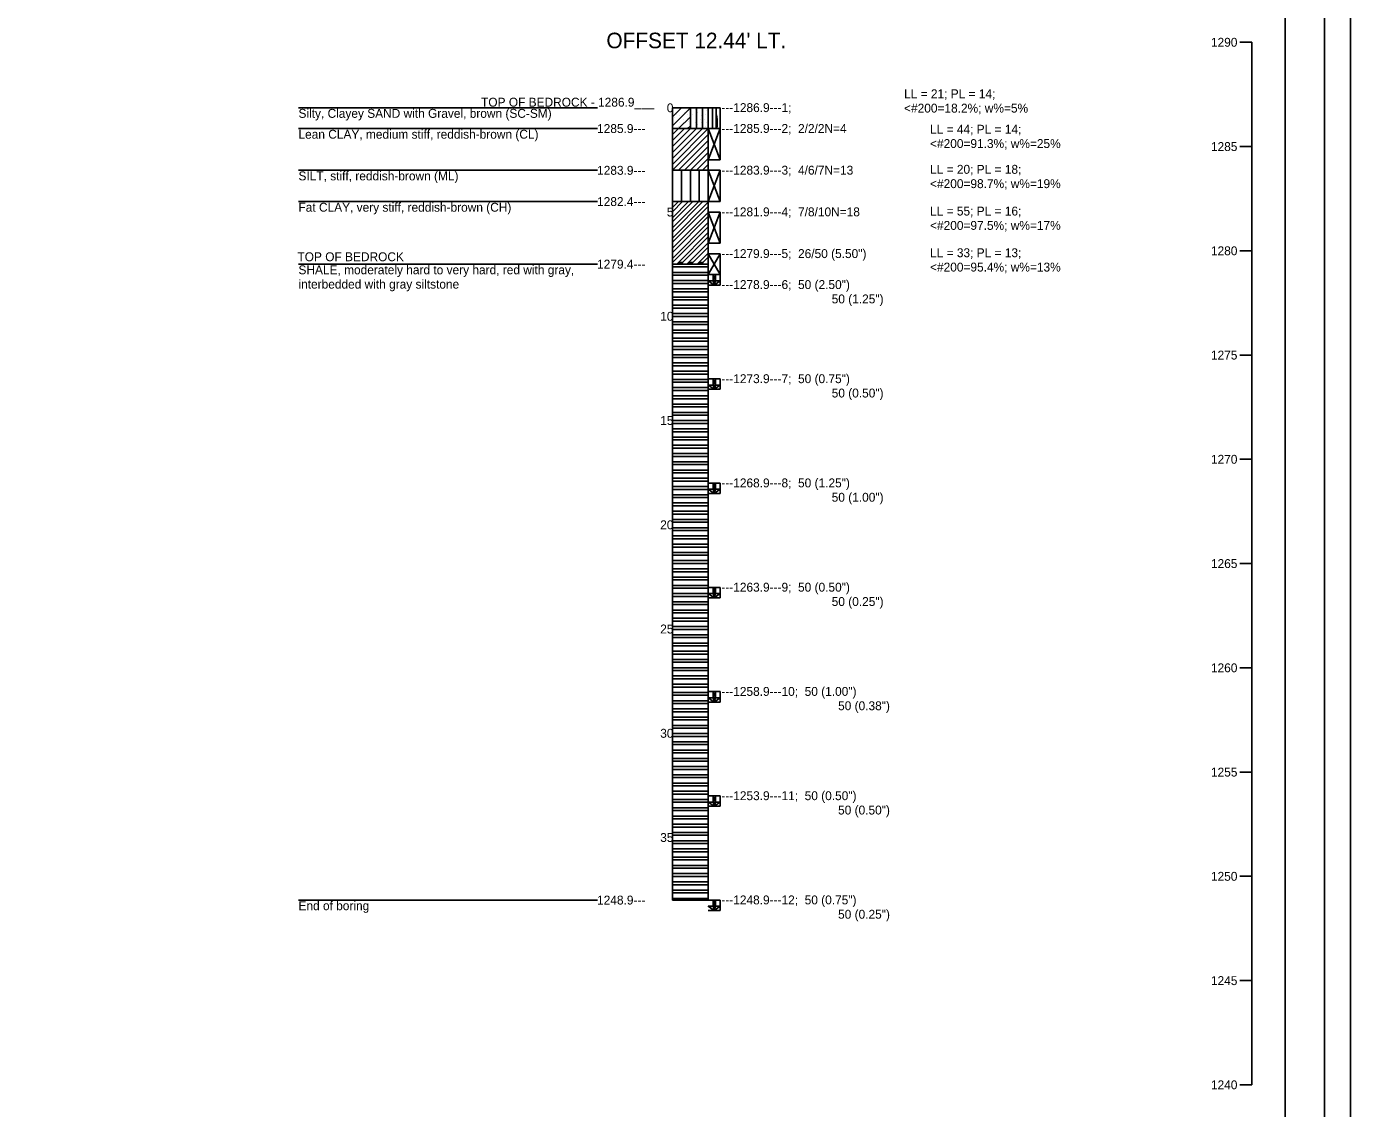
# Model space of a CAD drawing. Extents: x -6 to 173, y 24 to 64.
# Drawn here: x 24.17 to 42.62, y 35.63 to 50.71 of the extents above; entities that cross this region are included whole.
import ezdxf

# ---------------------------------------------------------------- set-up
doc = ezdxf.new("R2010")
doc.units = 0
for name, color, linetype in [('SHT_Plot_Shape_Full', 7, 'Continuous'), ('SHT_Plot_Shape_Half', 7, 'Continuous'), ('SHT_Sheet_Border', 7, 'Continuous')]:
    doc.layers.add(name, color=color, linetype=linetype)

# ---------------------------------------------------------------- blocks, each defined once
blk = doc.blocks.new('POINT_DISPLAY')
blk.add_line((0, 0), (0, 0))

msp = doc.modelspace()

# ---------------------------------------------------------------- linework, layer by layer
msp.add_line((41.25, 35.958), (41.25, 50.493))
for points in [[(41.25, 50.493), (41.083, 50.493)], [(27.961, 49.58), (32.127, 49.58)], [(33.173, 49.455), (33.298, 49.58)], [(33.173, 49.33), (33.423, 49.58)], [(33.173, 49.58), (33.173, 38.534)], [(33.173, 49.58), (33.673, 49.58)], [(33.423, 49.29), (33.423, 49.58)], [(33.507, 49.29), (33.507, 49.58)], [(33.59, 49.29), (33.59, 49.58)], [(33.673, 49.58), (33.84, 49.58)], [(33.673, 49.58), (33.673, 38.534)], [(33.84, 49.29), (33.84, 49.58)], [(27.961, 49.29), (32.127, 49.29)], [(33.173, 49.29), (33.673, 49.29)], [(33.173, 49.206), (33.257, 49.29)], [(33.173, 49.123), (33.34, 49.29)], [(33.173, 49.04), (33.423, 49.29)], [(33.173, 48.956), (33.507, 49.29)], [(33.173, 48.873), (33.59, 49.29)], [(33.173, 48.79), (33.673, 49.29)], [(33.257, 49.29), (33.423, 49.455)], [(33.382, 49.29), (33.423, 49.33)], [(33.673, 49.29), (33.84, 49.29)], [(33.673, 49.29), (33.84, 48.854)], [(33.673, 48.854), (33.84, 49.29)], [(33.673, 49.29), (33.84, 49.29)], [(33.84, 48.854), (33.84, 49.29)], [(33.175, 48.708), (33.673, 49.206)], [(33.258, 48.708), (33.673, 49.123)], [(33.342, 48.708), (33.673, 49.04)], [(33.425, 48.708), (33.673, 48.956)], [(41.25, 49.039), (41.083, 49.039)], [(33.508, 48.708), (33.673, 48.873)], [(33.592, 48.708), (33.673, 48.79)], [(33.673, 48.854), (33.84, 48.854)], [(27.961, 48.708), (32.127, 48.708)], [(33.173, 48.708), (33.673, 48.708)], [(33.298, 48.272), (33.298, 48.708)], [(33.423, 48.272), (33.423, 48.708)], [(33.548, 48.272), (33.548, 48.708)], [(33.673, 48.708), (33.84, 48.272)], [(33.673, 48.272), (33.84, 48.708)], [(33.673, 48.708), (33.84, 48.708)], [(33.84, 48.272), (33.84, 48.708)], [(27.961, 48.272), (32.127, 48.272)], [(33.173, 48.272), (33.673, 48.272)], [(33.673, 48.272), (33.84, 48.272)], [(33.673, 48.127), (33.84, 47.691)], [(33.673, 47.691), (33.84, 48.127)], [(33.673, 48.127), (33.84, 48.127)], [(33.84, 47.691), (33.84, 48.127)], [(33.673, 47.691), (33.84, 47.691)], [(33.673, 47.545), (33.84, 47.255)], [(33.673, 47.255), (33.84, 47.545)], [(33.673, 47.545), (33.84, 47.545)], [(33.84, 47.255), (33.84, 47.545)], [(41.25, 47.586), (41.083, 47.586)], [(27.961, 47.4), (32.127, 47.4)], [(33.173, 47.4), (33.673, 47.4)], [(33.173, 47.4), (33.673, 47.4)], [(33.173, 47.361), (33.673, 47.361)], [(33.173, 47.285), (33.673, 47.285)], [(33.173, 47.246), (33.673, 47.246)], [(33.673, 47.255), (33.84, 47.255)], [(33.673, 47.255), (33.84, 47.255)], [(33.84, 47.109), (33.84, 47.255)], [(33.173, 47.17), (33.673, 47.17)], [(33.173, 47.131), (33.673, 47.131)], [(33.673, 47.109), (33.84, 47.109)], [(33.173, 47.056), (33.673, 47.056)], [(33.173, 47.016), (33.673, 47.016)], [(33.173, 46.941), (33.673, 46.941)], [(33.173, 46.901), (33.673, 46.901)], [(33.173, 46.826), (33.673, 46.826)], [(33.173, 46.787), (33.673, 46.787)], [(33.173, 46.711), (33.673, 46.711)], [(33.173, 46.672), (33.673, 46.672)], [(33.173, 46.596), (33.673, 46.596)], [(33.173, 46.557), (33.673, 46.557)], [(33.173, 46.481), (33.673, 46.481)], [(33.173, 46.442), (33.673, 46.442)], [(33.173, 46.367), (33.673, 46.367)], [(33.173, 46.327), (33.673, 46.327)], [(33.173, 46.252), (33.673, 46.252)], [(33.173, 46.212), (33.673, 46.212)], [(33.173, 46.137), (33.673, 46.137)], [(33.173, 46.098), (33.673, 46.098)], [(33.173, 46.022), (33.673, 46.022)], [(33.173, 45.983), (33.673, 45.983)], [(41.25, 46.132), (41.083, 46.132)], [(33.173, 45.907), (33.673, 45.907)], [(33.173, 45.868), (33.673, 45.868)], [(33.173, 45.792), (33.673, 45.792)], [(33.673, 45.801), (33.84, 45.801)], [(33.84, 45.656), (33.84, 45.801)], [(33.173, 45.753), (33.673, 45.753)], [(33.173, 45.678), (33.673, 45.678)], [(33.173, 45.638), (33.673, 45.638)], [(33.673, 45.656), (33.84, 45.656)], [(33.173, 45.563), (33.673, 45.563)], [(33.173, 45.523), (33.673, 45.523)], [(33.173, 45.448), (33.673, 45.448)], [(33.173, 45.409), (33.673, 45.409)], [(33.173, 45.333), (33.673, 45.333)], [(33.173, 45.294), (33.673, 45.294)], [(33.173, 45.218), (33.673, 45.218)], [(33.173, 45.179), (33.673, 45.179)], [(33.173, 45.103), (33.673, 45.103)], [(33.173, 45.064), (33.673, 45.064)], [(33.173, 44.989), (33.673, 44.989)], [(33.173, 44.949), (33.673, 44.949)], [(33.173, 44.874), (33.673, 44.874)], [(33.173, 44.834), (33.673, 44.834)], [(33.173, 44.759), (33.673, 44.759)], [(33.173, 44.72), (33.673, 44.72)], [(41.25, 44.679), (41.083, 44.679)], [(33.173, 44.644), (33.673, 44.644)], [(33.173, 44.605), (33.673, 44.605)], [(33.173, 44.529), (33.673, 44.529)], [(33.173, 44.49), (33.673, 44.49)], [(33.173, 44.414), (33.673, 44.414)], [(33.173, 44.375), (33.673, 44.375)], [(33.173, 44.3), (33.673, 44.3)], [(33.673, 44.348), (33.84, 44.348)], [(33.84, 44.202), (33.84, 44.348)], [(33.173, 44.26), (33.673, 44.26)], [(33.173, 44.185), (33.673, 44.185)], [(33.173, 44.145), (33.673, 44.145)], [(33.673, 44.202), (33.84, 44.202)], [(33.173, 44.07), (33.673, 44.07)], [(33.173, 44.031), (33.673, 44.031)], [(33.173, 43.955), (33.673, 43.955)], [(33.173, 43.916), (33.673, 43.916)], [(33.173, 43.84), (33.673, 43.84)], [(33.173, 43.801), (33.673, 43.801)], [(33.173, 43.726), (33.673, 43.726)], [(33.173, 43.686), (33.673, 43.686)], [(33.173, 43.611), (33.673, 43.611)], [(33.173, 43.571), (33.673, 43.571)], [(33.173, 43.496), (33.673, 43.496)], [(33.173, 43.456), (33.673, 43.456)], [(33.173, 43.381), (33.673, 43.381)], [(33.173, 43.342), (33.673, 43.342)], [(33.173, 43.266), (33.673, 43.266)], [(33.173, 43.227), (33.673, 43.227)], [(41.25, 43.225), (41.083, 43.225)], [(33.173, 43.151), (33.673, 43.151)], [(33.173, 43.112), (33.673, 43.112)], [(33.173, 43.037), (33.673, 43.037)], [(33.173, 42.997), (33.673, 42.997)], [(33.173, 42.922), (33.673, 42.922)], [(33.173, 42.882), (33.673, 42.882)], [(33.673, 42.894), (33.84, 42.894)], [(33.84, 42.749), (33.84, 42.894)], [(33.173, 42.807), (33.673, 42.807)], [(33.173, 42.768), (33.673, 42.768)], [(33.173, 42.692), (33.673, 42.692)], [(33.173, 42.653), (33.673, 42.653)], [(33.673, 42.749), (33.84, 42.749)], [(33.173, 42.577), (33.673, 42.577)], [(33.173, 42.538), (33.673, 42.538)], [(33.173, 42.462), (33.673, 42.462)], [(33.173, 42.423), (33.673, 42.423)], [(33.173, 42.348), (33.673, 42.348)], [(33.173, 42.308), (33.673, 42.308)], [(33.173, 42.233), (33.673, 42.233)], [(33.173, 42.193), (33.673, 42.193)], [(33.173, 42.118), (33.673, 42.118)], [(33.173, 42.079), (33.673, 42.079)], [(33.173, 42.003), (33.673, 42.003)], [(33.173, 41.964), (33.673, 41.964)], [(33.173, 41.888), (33.673, 41.888)], [(33.173, 41.849), (33.673, 41.849)], [(33.173, 41.773), (33.673, 41.773)], [(33.173, 41.734), (33.673, 41.734)], [(41.25, 41.772), (41.083, 41.772)], [(33.173, 41.659), (33.673, 41.659)], [(33.173, 41.619), (33.673, 41.619)], [(33.173, 41.544), (33.673, 41.544)], [(33.173, 41.504), (33.673, 41.504)], [(33.173, 41.429), (33.673, 41.429)], [(33.173, 41.39), (33.673, 41.39)], [(33.673, 41.441), (33.84, 41.441)], [(33.84, 41.295), (33.84, 41.441)], [(33.173, 41.314), (33.673, 41.314)], [(33.173, 41.275), (33.673, 41.275)], [(33.173, 41.199), (33.673, 41.199)], [(33.173, 41.16), (33.673, 41.16)], [(33.673, 41.295), (33.84, 41.295)], [(33.173, 41.084), (33.673, 41.084)], [(33.173, 41.045), (33.673, 41.045)], [(33.173, 40.97), (33.673, 40.97)], [(33.173, 40.93), (33.673, 40.93)], [(33.173, 40.855), (33.673, 40.855)], [(33.173, 40.815), (33.673, 40.815)], [(33.173, 40.74), (33.673, 40.74)], [(33.173, 40.701), (33.673, 40.701)], [(33.173, 40.625), (33.673, 40.625)], [(33.173, 40.586), (33.673, 40.586)], [(33.173, 40.51), (33.673, 40.51)], [(33.173, 40.471), (33.673, 40.471)], [(33.173, 40.395), (33.673, 40.395)], [(33.173, 40.356), (33.673, 40.356)], [(33.173, 40.281), (33.673, 40.281)], [(33.173, 40.241), (33.673, 40.241)], [(41.25, 40.318), (41.083, 40.318)], [(33.173, 40.166), (33.673, 40.166)], [(33.173, 40.126), (33.673, 40.126)], [(33.173, 40.051), (33.673, 40.051)], [(33.173, 40.012), (33.673, 40.012)], [(33.173, 39.936), (33.673, 39.936)], [(33.173, 39.897), (33.673, 39.897)], [(33.673, 39.987), (33.84, 39.987)], [(33.84, 39.842), (33.84, 39.987)], [(33.173, 39.821), (33.673, 39.821)], [(33.173, 39.782), (33.673, 39.782)], [(33.173, 39.706), (33.673, 39.706)], [(33.673, 39.842), (33.84, 39.842)], [(33.173, 39.667), (33.673, 39.667)], [(33.173, 39.592), (33.673, 39.592)], [(33.173, 39.552), (33.673, 39.552)], [(33.173, 39.477), (33.673, 39.477)], [(33.173, 39.437), (33.673, 39.437)], [(33.173, 39.362), (33.673, 39.362)], [(33.173, 39.323), (33.673, 39.323)], [(33.173, 39.247), (33.673, 39.247)], [(33.173, 39.208), (33.673, 39.208)], [(33.173, 39.132), (33.673, 39.132)], [(33.173, 39.093), (33.673, 39.093)], [(33.173, 39.018), (33.673, 39.018)], [(33.173, 38.978), (33.673, 38.978)], [(33.173, 38.903), (33.673, 38.903)], [(33.173, 38.863), (33.673, 38.863)], [(33.173, 38.788), (33.673, 38.788)], [(41.25, 38.865), (41.083, 38.865)], [(33.173, 38.748), (33.673, 38.748)], [(33.173, 38.673), (33.673, 38.673)], [(33.173, 38.634), (33.673, 38.634)], [(27.961, 38.534), (32.127, 38.534)], [(33.173, 38.558), (33.673, 38.558)], [(33.173, 38.534), (33.673, 38.534)], [(33.673, 38.534), (33.84, 38.534)], [(33.673, 38.388), (33.84, 38.388)], [(33.84, 38.388), (33.84, 38.534)], [(41.25, 37.411), (41.083, 37.411)], [(41.25, 35.958), (41.083, 35.958)]]:
    msp.add_lwpolyline(points)
for points in [[(33.732, 49.58), (33.732, 49.29), (33.782, 49.29), (33.782, 49.58)], [(33.796, 49.414), (33.79, 49.455), (33.782, 49.495), (33.796, 49.414)], [(33.782, 49.495), (33.782, 49.29), (33.796, 49.414), (33.782, 49.495)], [(33.782, 49.29), (33.796, 49.33), (33.796, 49.414), (33.782, 49.29)], [(33.782, 49.29), (33.79, 49.29), (33.796, 49.33), (33.782, 49.29)], [(33.796, 49.33), (33.798, 49.372), (33.796, 49.414), (33.796, 49.33)], [(33.173, 47.905), (33.54, 48.272), (33.598, 48.272), (33.173, 47.847)], [(33.173, 48.047), (33.398, 48.272), (33.457, 48.272), (33.173, 47.989)], [(33.173, 48.189), (33.257, 48.272), (33.315, 48.272), (33.173, 48.13)], [(33.673, 48.206), (33.673, 48.264), (33.173, 47.764), (33.173, 47.705)], [(33.673, 48.064), (33.673, 48.122), (33.173, 47.622), (33.173, 47.564)], [(33.673, 47.922), (33.673, 47.981), (33.173, 47.48), (33.173, 47.422)], [(33.315, 47.422), (33.673, 47.78), (33.673, 47.839), (33.257, 47.422)], [(33.457, 47.422), (33.673, 47.639), (33.673, 47.697), (33.398, 47.422)], [(33.598, 47.422), (33.673, 47.497), (33.673, 47.555), (33.54, 47.422)], [(33.315, 47.422), (33.257, 47.422), (33.234, 47.4), (33.293, 47.4)], [(33.457, 47.422), (33.398, 47.422), (33.376, 47.4), (33.434, 47.4)], [(33.598, 47.422), (33.54, 47.422), (33.518, 47.4), (33.576, 47.4)], [(33.659, 47.4), (33.673, 47.4), (33.673, 47.414), (33.659, 47.4)], [(33.74, 47.167), (33.773, 47.167), (33.773, 47.255), (33.74, 47.167)], [(33.74, 47.167), (33.773, 47.255), (33.74, 47.255), (33.74, 47.167)], [(33.74, 47.167), (33.673, 47.167), (33.757, 47.109), (33.74, 47.167)], [(33.74, 47.167), (33.757, 47.109), (33.773, 47.167), (33.74, 47.167)], [(33.757, 47.109), (33.84, 47.167), (33.773, 47.167), (33.757, 47.109)], [(33.74, 45.714), (33.773, 45.714), (33.773, 45.801), (33.74, 45.714)], [(33.74, 45.714), (33.773, 45.801), (33.74, 45.801), (33.74, 45.714)], [(33.74, 45.714), (33.673, 45.714), (33.757, 45.656), (33.74, 45.714)], [(33.74, 45.714), (33.757, 45.656), (33.773, 45.714), (33.74, 45.714)], [(33.757, 45.656), (33.84, 45.714), (33.773, 45.714), (33.757, 45.656)], [(33.74, 44.261), (33.773, 44.261), (33.773, 44.348), (33.74, 44.261)], [(33.74, 44.261), (33.773, 44.348), (33.74, 44.348), (33.74, 44.261)], [(33.74, 44.261), (33.673, 44.261), (33.757, 44.202), (33.74, 44.261)], [(33.74, 44.261), (33.757, 44.202), (33.773, 44.261), (33.74, 44.261)], [(33.757, 44.202), (33.84, 44.261), (33.773, 44.261), (33.757, 44.202)], [(33.74, 42.807), (33.773, 42.807), (33.773, 42.894), (33.74, 42.807)], [(33.74, 42.807), (33.773, 42.894), (33.74, 42.894), (33.74, 42.807)], [(33.74, 42.807), (33.673, 42.807), (33.757, 42.749), (33.74, 42.807)], [(33.74, 42.807), (33.757, 42.749), (33.773, 42.807), (33.74, 42.807)], [(33.757, 42.749), (33.84, 42.807), (33.773, 42.807), (33.757, 42.749)], [(33.74, 41.354), (33.673, 41.354), (33.757, 41.295), (33.74, 41.354)], [(33.74, 41.354), (33.773, 41.354), (33.773, 41.441), (33.74, 41.354)], [(33.74, 41.354), (33.773, 41.441), (33.74, 41.441), (33.74, 41.354)], [(33.74, 41.354), (33.757, 41.295), (33.773, 41.354), (33.74, 41.354)], [(33.757, 41.295), (33.84, 41.354), (33.773, 41.354), (33.757, 41.295)], [(33.74, 39.9), (33.673, 39.9), (33.757, 39.842), (33.74, 39.9)], [(33.74, 39.9), (33.773, 39.9), (33.773, 39.987), (33.74, 39.9)], [(33.74, 39.9), (33.773, 39.987), (33.74, 39.987), (33.74, 39.9)], [(33.74, 39.9), (33.757, 39.842), (33.773, 39.9), (33.74, 39.9)], [(33.757, 39.842), (33.84, 39.9), (33.773, 39.9), (33.757, 39.842)], [(33.74, 38.447), (33.673, 38.447), (33.757, 38.388), (33.74, 38.447)], [(33.74, 38.447), (33.773, 38.447), (33.773, 38.534), (33.74, 38.447)], [(33.74, 38.447), (33.773, 38.534), (33.74, 38.534), (33.74, 38.447)], [(33.74, 38.447), (33.757, 38.388), (33.773, 38.447), (33.74, 38.447)], [(33.757, 38.388), (33.84, 38.447), (33.773, 38.447), (33.757, 38.388)]]:
    msp.add_lwpolyline(points, close=True)
at = {"layer": 'SHT_Plot_Shape_Full'}
msp.add_lwpolyline([(6.624, 53.971), (42.624, 53.971), (42.624, 29.971), (6.624, 29.971)], close=True, dxfattribs=at)
at = {"layer": 'SHT_Plot_Shape_Half'}
msp.add_lwpolyline([(8.262, 53.146), (42.262, 53.146), (42.262, 31.146), (8.262, 31.146)], close=True, dxfattribs=at)
at = {"layer": 'SHT_Sheet_Border'}
msp.add_lwpolyline([(10.212, 52.646), (41.712, 52.646), (41.712, 31.646), (10.212, 31.646)], close=True, dxfattribs=at)

# ---------------------------------------------------------------- block references
at = {"xscale": 0.01, "yscale": 0.01}
for p in [(33.178, 49.518), (33.203, 49.568), (33.228, 49.493), (33.253, 49.543), (33.278, 49.468), (33.328, 49.568), (33.345, 49.52), (33.378, 49.493), (33.403, 49.543), (33.453, 49.493), (33.492, 49.555), (33.528, 49.518), (33.578, 49.568), (33.578, 49.468), (33.628, 49.493), (33.653, 49.543), (33.178, 49.343), (33.203, 49.443), (33.228, 49.393), (33.253, 49.318), (33.278, 49.368), (33.303, 49.293), (33.328, 49.418), (33.341, 49.36), (33.38, 49.308), (33.39, 49.436), (33.403, 49.393), (33.428, 49.318), (33.478, 49.293), (33.491, 49.379), (33.503, 49.443), (33.528, 49.343), (33.559, 49.414), (33.578, 49.368), (33.62, 49.411), (33.628, 49.318), (33.653, 49.368), (33.669, 49.418)]:
    msp.add_blockref('POINT_DISPLAY', p, dxfattribs=at)

# ---------------------------------------------------------------- texts
for s, height, p in [("OFFSET 12.44' LT.", 0.217, (32.253, 50.41)), ('1290', 0.124, (40.679, 50.431)), ('LL = 21; PL = 14;', 0.124, (36.402, 49.713)), ('TOP OF BEDROCK - 1286.9___', 0.124, (30.506, 49.596)), ('0', 0.124, (33.095, 49.518)), ('---1286.9---1;', 0.124, (33.855, 49.52)), ('Silty, Clayey SAND with Gravel, brown (SC-SM)', 0.124, (27.961, 49.44)), ('<#200=18.2%; w%=5%', 0.124, (36.402, 49.513)), ('Lean CLAY, medium stiff, reddish-brown (CL)', 0.124, (27.961, 49.149)), ('1285.9---', 0.124, (32.123, 49.228)), ('---1285.9---2;  2/2/2N=4', 0.124, (33.855, 49.23)), ('LL = 44; PL = 14;', 0.124, (36.764, 49.219)), ('<#200=91.3%; w%=25%', 0.124, (36.764, 49.019)), ('1285', 0.124, (40.679, 48.977)), ('1283.9---', 0.124, (32.123, 48.646)), ('---1283.9---3;  4/6/7N=13', 0.124, (33.855, 48.648)), ('LL = 20; PL = 18;', 0.124, (36.764, 48.66)), ('SILT, stiff, reddish-brown (ML)', 0.124, (27.961, 48.568)), ('<#200=98.7%; w%=19%', 0.124, (36.764, 48.46)), ('Fat CLAY, very stiff, reddish-brown (CH)', 0.124, (27.961, 48.131)), ('1282.4---', 0.124, (32.123, 48.21)), ('5', 0.124, (33.095, 48.065)), ('---1281.9---4;  7/8/10N=18', 0.124, (33.855, 48.067)), ('LL = 55; PL = 16;', 0.124, (36.764, 48.078)), ('<#200=97.5%; w%=17%', 0.124, (36.764, 47.878)), ('---1279.9---5;  26/50 (5.50")', 0.124, (33.855, 47.485)), ('LL = 33; PL = 13;', 0.124, (36.764, 47.497)), ('1280', 0.124, (40.679, 47.524)), ('TOP OF BEDROCK', 0.124, (27.947, 47.441)), ('1279.4---', 0.124, (32.123, 47.338)), ('SHALE, moderately hard to very hard, red with gray,', 0.124, (27.961, 47.259)), ('<#200=95.4%; w%=13%', 0.124, (36.764, 47.297)), ('interbedded with gray siltstone', 0.124, (27.961, 47.059)), ('---1278.9---6;  50 (2.50")', 0.124, (33.855, 47.053)), ('50 (1.25")', 0.124, (35.393, 46.853)), ('10', 0.124, (33.003, 46.611)), ('1275', 0.124, (40.679, 46.07)), ('---1273.9---7;  50 (0.75")', 0.124, (33.855, 45.741)), ('50 (0.50")', 0.124, (35.393, 45.541)), ('15', 0.124, (33.003, 45.158)), ('1270', 0.124, (40.679, 44.617)), ('---1268.9---8;  50 (1.25")', 0.124, (33.855, 44.288)), ('50 (1.00")', 0.124, (35.393, 44.088)), ('20', 0.124, (33.003, 43.704)), ('1265', 0.124, (40.679, 43.163)), ('---1263.9---9;  50 (0.50")', 0.124, (33.855, 42.834)), ('50 (0.25")', 0.124, (35.393, 42.634)), ('25', 0.124, (33.003, 42.251)), ('1260', 0.124, (40.679, 41.71)), ('---1258.9---10;  50 (1.00")', 0.124, (33.855, 41.381)), ('50 (0.38")', 0.124, (35.482, 41.181)), ('30', 0.124, (33.003, 40.797)), ('1255', 0.124, (40.679, 40.256)), ('---1253.9---11;  50 (0.50")', 0.124, (33.855, 39.927)), ('50 (0.50")', 0.124, (35.482, 39.727)), ('35', 0.124, (33.003, 39.344)), ('1250', 0.124, (40.679, 38.803)), ('1248.9---', 0.124, (32.123, 38.472)), ('---1248.9---12;  50 (0.75")', 0.124, (33.855, 38.474)), ('End of boring', 0.124, (27.961, 38.393)), ('50 (0.25")', 0.124, (35.482, 38.274)), ('1245', 0.124, (40.679, 37.349)), ('1240', 0.124, (40.679, 35.896))]:
    msp.add_text(s, height=height).set_placement(p)

doc.saveas('drawing.dxf')
